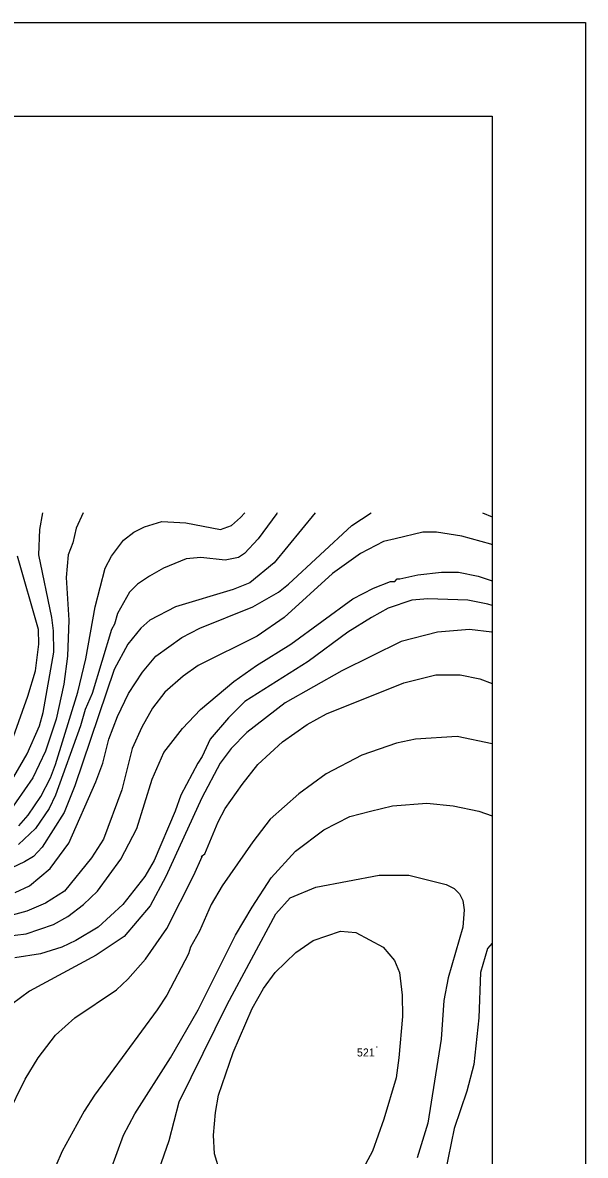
# Model space of a CAD drawing. Extents: x -510989 to -501240, y -1184665 to -1176089.
# Drawn here: x -508441 to -508019, y -1176947 to -1176098 of the extents above; entities that cross this region are included whole.
import ezdxf

# ---------------------------------------------------------------- set-up
doc = ezdxf.new("R2010")
doc.units = 0
for name, color, linetype in [('rozpiska', 7, 'Continuous'), ('vrstevnice_01', 7, 'Continuous'), ('vrstevnice_02', 7, 'Continuous'), ('vrstevnice_03', 7, 'Continuous'), ('vrstevnice_05', 7, 'Continuous')]:
    doc.layers.add(name, color=color, linetype=linetype)

msp = doc.modelspace()

# ---------------------------------------------------------------- linework, layer by layer
at = {"layer": 'rozpiska'}
for points in [[(-508019.09, -1176098), (-508019.09, -1184498), (-510989.09, -1184498), (-510989.09, -1176098)], [(-508089.09, -1176168), (-508089.09, -1184428), (-510919.09, -1184428), (-510919.09, -1176168)]]:
    msp.add_lwpolyline(points, close=True, dxfattribs=at)
at = {"layer": 'vrstevnice_01'}
for points in [[(-508395.61, -1176465.53), (-508400.91, -1176477), (-508403.41, -1176488), (-508406.81, -1176497), (-508408.31, -1176514), (-508406.41, -1176546), (-508407.31, -1176573), (-508410.09, -1176594), (-508416, -1176620), (-508423.91, -1176644), (-508433.41, -1176664), (-508452.09, -1176691), (-508460.19, -1176698), (-508465.31, -1176700), (-508475.81, -1176701), (-508488.31, -1176699), (-508514.91, -1176688)], [(-508446.59, -1176750), (-508436, -1176745), (-508420.5, -1176732), (-508406.41, -1176713), (-508386.19, -1176667), (-508380.81, -1176653), (-508376.31, -1176635), (-508369.91, -1176618), (-508361.59, -1176601), (-508351.09, -1176585), (-508341.19, -1176573), (-508321.59, -1176559), (-508308.31, -1176552), (-508268.5, -1176536), (-508249.31, -1176525), (-508241.59, -1176519), (-508194.31, -1176475), (-508179.76, -1176465.53)], [(-508250.26, -1176465.53), (-508250.5, -1176466), (-508264.5, -1176485), (-508274.59, -1176496), (-508279.31, -1176499), (-508289.09, -1176501), (-508307.5, -1176499), (-508318.41, -1176500), (-508335.41, -1176507), (-508345.81, -1176513), (-508354.81, -1176519), (-508360.81, -1176525), (-508369.91, -1176541), (-508372.09, -1176549), (-508374.5, -1176553), (-508388.91, -1176601), (-508394.09, -1176613), (-508397.69, -1176625), (-508416.31, -1176677), (-508421.09, -1176687), (-508431.31, -1176702), (-508444.19, -1176714)], [(-508096.26, -1176465.53), (-508089.09, -1176468.46)], [(-508448, -1176633), (-508437.09, -1176603), (-508431.41, -1176584), (-508428.81, -1176564), (-508429.19, -1176553), (-508445, -1176498)], [(-508455, -1176783), (-508438.5, -1176781), (-508417.81, -1176774), (-508407.09, -1176768), (-508395.5, -1176759), (-508385, -1176749), (-508367.31, -1176725), (-508355.5, -1176702), (-508344, -1176665), (-508335.19, -1176645), (-508321.09, -1176627), (-508307.81, -1176613), (-508282.59, -1176592), (-508265.59, -1176580), (-508240, -1176564), (-508193.41, -1176530), (-508177.91, -1176522), (-508165.19, -1176517), (-508162, -1176517), (-508160.31, -1176515), (-508158.09, -1176515), (-508144.81, -1176512), (-508126.91, -1176510), (-508114.19, -1176510), (-508099.59, -1176513), (-508089.09, -1176516.41)], [(-508089.09, -1176555.06), (-508089.31, -1176555), (-508105.91, -1176553), (-508130, -1176555), (-508157.09, -1176562), (-508201.81, -1176584), (-508244.19, -1176608), (-508272.91, -1176630), (-508284.81, -1176642), (-508292.91, -1176653), (-508306.69, -1176679), (-508333.69, -1176738), (-508345.41, -1176760), (-508364.81, -1176783), (-508386, -1176797), (-508435.81, -1176824), (-508449.5, -1176834), (-508464.09, -1176851), (-508473.09, -1176870), (-508480.13, -1176891.88)], [(-508089.09, -1176638.59), (-508115.31, -1176633), (-508146.5, -1176635), (-508160.69, -1176638), (-508186.81, -1176647), (-508213.41, -1176661), (-508234, -1176676), (-508255.5, -1176695), (-508268.5, -1176712), (-508291.41, -1176745), (-508299.59, -1176759), (-508308.41, -1176779), (-508315.09, -1176791), (-508316.59, -1176796), (-508333, -1176827), (-508340.09, -1176838), (-508387.19, -1176902), (-508394.81, -1176914), (-508411.5, -1176944), (-508420.81, -1176966)], [(-508283.31, -1176870), (-508269, -1176837), (-508260.5, -1176822), (-508251.81, -1176810), (-508236.19, -1176795), (-508223.31, -1176786), (-508202.69, -1176779), (-508191.09, -1176780), (-508170.81, -1176791), (-508162.09, -1176801), (-508158.5, -1176810), (-508156.5, -1176827), (-508156.09, -1176843), (-508158.91, -1176874), (-508161, -1176889), (-508170.09, -1176920), (-508178.81, -1176944), (-508185.81, -1176957)], [(-508292.91, -1176960), (-508297.09, -1176946), (-508298, -1176932), (-508296.5, -1176915), (-508294.09, -1176902), (-508283.31, -1176870)]]:
    msp.add_lwpolyline(points, dxfattribs=at)
at = {"layer": 'vrstevnice_02'}
for points in [[(-508221.66, -1176465.53), (-508252.5, -1176503), (-508270.81, -1176518), (-508283.09, -1176523), (-508326.5, -1176536), (-508345.59, -1176546), (-508352.31, -1176552), (-508362.09, -1176564), (-508372.31, -1176583), (-508402, -1176670), (-508410, -1176690), (-508426.5, -1176716), (-508433, -1176723), (-508439.59, -1176727), (-508459, -1176736)], [(-508450.5, -1176668), (-508437.59, -1176646), (-508428.31, -1176625), (-508425.69, -1176615), (-508417.59, -1176570), (-508418, -1176554), (-508419.09, -1176544), (-508429, -1176497), (-508428.09, -1176478), (-508425.83, -1176465.53)], [(-508443.91, -1176700), (-508436.81, -1176692), (-508427.5, -1176678), (-508420.09, -1176664), (-508416.31, -1176654), (-508399.69, -1176600), (-508393.69, -1176575), (-508386.69, -1176536), (-508379.09, -1176507), (-508374.41, -1176498), (-508365.31, -1176486), (-508357.59, -1176480), (-508349.59, -1176476), (-508336.59, -1176472), (-508318.59, -1176473), (-508292.59, -1176478), (-508284.41, -1176475), (-508277.81, -1176469), (-508274.46, -1176465.53)], [(-508089.09, -1176489.4), (-508089.91, -1176489), (-508111.81, -1176483), (-508130.59, -1176480), (-508141, -1176480), (-508161.69, -1176485), (-508170.5, -1176487), (-508187.81, -1176496), (-508208.81, -1176511), (-508244.91, -1176544), (-508265.31, -1176558), (-508309.41, -1176580), (-508320.69, -1176588), (-508334.41, -1176600), (-508343.69, -1176612), (-508351.59, -1176626), (-508358.91, -1176642), (-508366.69, -1176673), (-508380.41, -1176710), (-508389.31, -1176724), (-508409.59, -1176749), (-508423.91, -1176758), (-508437.91, -1176764), (-508448.81, -1176767)], [(-508089.09, -1176534.98), (-508092.31, -1176534), (-508107.19, -1176531), (-508137.19, -1176530), (-508149.31, -1176531), (-508166.91, -1176537), (-508179.41, -1176544), (-508197.09, -1176555), (-508227, -1176577), (-508274.41, -1176607), (-508286.81, -1176619), (-508300.41, -1176635), (-508306.41, -1176648), (-508309.81, -1176653), (-508322.41, -1176677), (-508326.81, -1176689), (-508342.5, -1176726), (-508349.5, -1176738), (-508365.91, -1176759), (-508384.5, -1176776), (-508401.09, -1176786), (-508411.69, -1176791), (-508427.59, -1176796), (-508446.91, -1176799)], [(-508452.91, -1176918), (-508439.09, -1176890), (-508429.41, -1176874), (-508416.31, -1176857), (-508401.81, -1176844), (-508370.69, -1176823), (-508362.19, -1176815), (-508348.81, -1176800), (-508333, -1176777), (-508312.59, -1176737), (-508306.41, -1176723), (-508307.31, -1176723), (-508304.5, -1176721), (-508294.5, -1176697), (-508289.09, -1176687), (-508276.5, -1176669), (-508264.59, -1176654), (-508246.19, -1176637), (-508227.59, -1176624), (-508213.31, -1176616), (-508155.09, -1176593), (-508131.31, -1176587), (-508113, -1176587), (-508098.31, -1176590), (-508089.09, -1176593.27)], [(-508374.81, -1176958), (-508365.41, -1176932), (-508357, -1176916), (-508330.19, -1176874), (-508309.41, -1176838), (-508281.41, -1176782), (-508269, -1176761), (-508254.69, -1176739), (-508236.41, -1176719), (-508215.31, -1176703), (-508195.69, -1176693), (-508180.19, -1176689), (-508163.81, -1176685), (-508137.91, -1176683), (-508118.19, -1176685), (-508099, -1176689), (-508089.09, -1176692.67)], [(-508089.09, -1176788), (-508092.59, -1176792), (-508097.69, -1176810), (-508098.91, -1176844), (-508102.81, -1176879), (-508108.09, -1176899), (-508117.5, -1176927), (-508128.69, -1176982), (-508131.31, -1176991), (-508133.81, -1176996), (-508137.31, -1177000), (-508146.41, -1177008), (-508163.31, -1177015), (-508194.69, -1177022), (-508213.41, -1177028), (-508243.69, -1177039)]]:
    msp.add_lwpolyline(points, dxfattribs=at)
at = {"layer": 'vrstevnice_03'}
for points in [[(-508251.09, -1176766), (-508240.41, -1176754), (-508221.31, -1176746), (-508173.81, -1176737), (-508151.5, -1176737), (-508123.41, -1176744), (-508117.41, -1176747), (-508113.41, -1176751), (-508111.09, -1176756), (-508110, -1176763), (-508111.09, -1176776), (-508121.91, -1176814), (-508125.19, -1176831), (-508127.31, -1176860), (-508137.09, -1176923), (-508145.31, -1176949)], [(-508344.41, -1176974), (-508331.09, -1176936), (-508323.69, -1176907), (-508287.81, -1176834), (-508251.09, -1176766)]]:
    msp.add_lwpolyline(points, dxfattribs=at)

# ---------------------------------------------------------------- texts
at = {"layer": 'vrstevnice_05'}
for s, p in [('521', (-508190.4, -1176872.97)), ('.', (-508176.68, -1176866.38))]:
    msp.add_text(s, height=6, dxfattribs=at).set_placement(p)

doc.saveas('drawing.dxf')
